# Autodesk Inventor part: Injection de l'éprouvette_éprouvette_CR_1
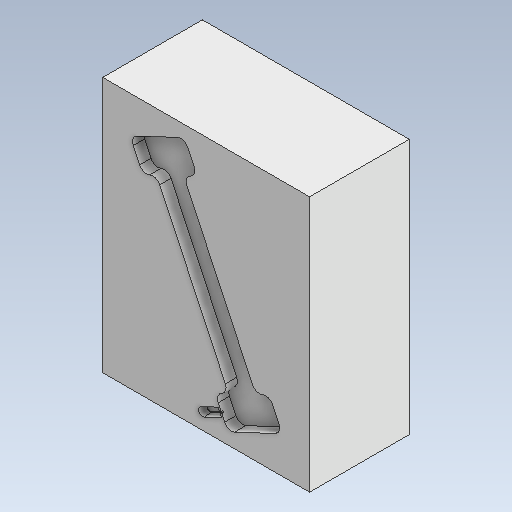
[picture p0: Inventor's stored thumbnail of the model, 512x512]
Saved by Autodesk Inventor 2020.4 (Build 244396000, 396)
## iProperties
Created: 2021-10
Part Number: Injection de l'éprouvette_éprouvette_CR_1
Material: Générique
Document SubType Name: Modeling
Designer: mel
Density: 1 g/cm^3
Appearance: Par défaut
Author: mel
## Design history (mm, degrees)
node "Injection de l'éprouvette_éprouvette_CR_Base"
feature "Sculpter1"
feature "Solide1::Injection de l'éprouvette_éprouvette_CR_Base"
tag "FonctionRepérage1"
node "Solide1"
feature "Injection de l'éprouvette_éprouvette_CR_Base_Corps"
feature "Surface1"
body "Srf1"
